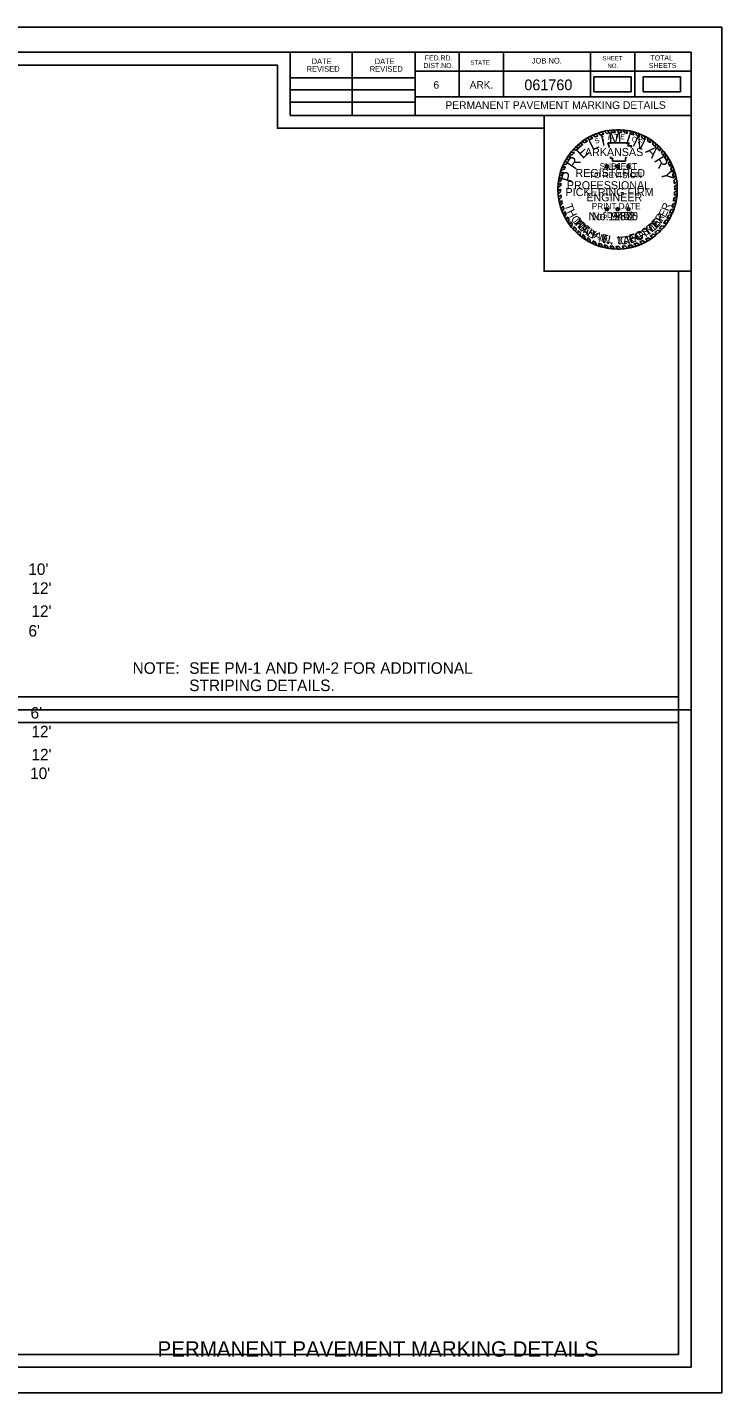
# Model space of a CAD drawing. Extents: x 1369905 to 1370238, y 380119 to 380332.
# Drawn here: x 1370129.6 to 1370238, y 380119.1 to 380332.4 of the extents above; entities that cross this region are included whole.
import ezdxf

# ---------------------------------------------------------------- set-up
doc = ezdxf.new("R2010")
doc.units = 0
for name, color, linetype in [('Default', 7, 'Continuous'), ('R_Border', 7, 'Continuous'), ('R_Border Notes', 7, 'Continuous'), ('R_Border Plan-Plan', 7, 'Continuous'), ('R_Border Title', 7, 'Continuous'), ('R_No Plot', 7, 'Continuous'), ('STAMP_PE_CRAFTON', 7, 'Continuous'), ('STAMP_PE_FOSTER', 7, 'Continuous'), ('STAMP_PE_SEAL-INFO', 7, 'Continuous'), ('STAMP_PE_TAEGTMEYER', 7, 'Continuous'), ('STAMP_PE_TXT', 7, 'Continuous'), ('STAMP_PRELIMINARY', 7, 'Continuous')]:
    doc.layers.add(name, color=color, linetype=linetype)

msp = doc.modelspace()

# ---------------------------------------------------------------- linework, layer by layer
at = {"layer": 'Default'}
for points in [[(1370218.08, 380322.36), (1370223.91, 380322.36), (1370223.91, 380324.67), (1370218.08, 380324.67)], [(1370225.75, 380322.36), (1370231.58, 380322.36), (1370231.58, 380324.67), (1370225.75, 380324.67)]]:
    msp.add_lwpolyline(points, close=True, dxfattribs=at)
at = {"layer": 'R_Border'}
for p, q in [((1369917.1, 380328.52), (1370233.28, 380328.52)), ((1370170.64, 380318.64), (1370170.64, 380328.52)), ((1370180.32, 380318.64), (1370180.32, 380328.52)), ((1370190.18, 380328.52), (1370190.18, 380318.64)), ((1370197.02, 380328.52), (1370197.02, 380321.58)), ((1370203.96, 380328.52), (1370203.96, 380321.58)), ((1370217.54, 380328.52), (1370217.54, 380321.58)), ((1370224.48, 380328.52), (1370224.48, 380321.58)), ((1370233.28, 380123.06), (1370233.28, 380328.52)), ((1370233.28, 380325.58), (1370190.18, 380325.58)), ((1370233.28, 380325.6), (1370233.28, 380325.6)), ((1370170.64, 380324.5), (1370190.18, 380324.5)), ((1370170.64, 380322.64), (1370190.18, 380322.64)), ((1370233.28, 380321.58), (1370190.18, 380321.58)), ((1370193.14, 380321.58), (1370233.28, 380321.58)), ((1370170.64, 380320.7), (1370190.18, 380320.7)), ((1370233.28, 380318.64), (1370170.64, 380318.64)), ((1370233.28, 380123.06), (1369917.1, 380123.06))]:
    msp.add_line(p, q, dxfattribs=at)
at = {"layer": 'R_Border Plan-Plan'}
msp.add_line((1369917.1, 380225.79), (1370233.28, 380225.79), dxfattribs=at)
at = {"layer": 'R_No Plot'}
for points in [[(1369904.69, 380332.42), (1370238.03, 380332.42), (1370238.03, 380119.08), (1369904.69, 380119.08)], [(1370231.28, 380227.79), (1369919.1, 380227.79), (1369919.1, 380326.52), (1370168.64, 380326.52), (1370168.64, 380316.64), (1370186.18, 380316.64), (1370210.28, 380316.64), (1370210.28, 380294.31), (1370231.28, 380294.31)], [(1369919.1, 380326.52), (1370168.64, 380326.52), (1370168.64, 380316.64), (1370186.18, 380316.64), (1370210.28, 380316.64), (1370210.28, 380294.31), (1370231.28, 380294.31), (1370231.28, 380125.06), (1369919.1, 380125.06)], [(1370210.28, 380318.64), (1370233.28, 380318.64), (1370233.28, 380294.31), (1370210.28, 380294.31)], [(1369919.1, 380223.79), (1370231.28, 380223.79), (1370231.28, 380125.06), (1369919.1, 380125.06)]]:
    msp.add_lwpolyline(points, close=True, dxfattribs=at)
at = {"layer": 'STAMP_PE_SEAL-INFO'}
for p, q in [((1370216.62, 380314.85), (1370217.06, 380314.65)), ((1370217, 380315.09), (1370217.43, 380314.87)), ((1370217.45, 380315.34), (1370217.91, 380315.12)), ((1370217.88, 380315.55), (1370218.27, 380315.28)), ((1370218.39, 380315.77), (1370218.68, 380315.44)), ((1370218.74, 380315.9), (1370219.12, 380315.59)), ((1370219.33, 380316.08), (1370219.62, 380315.73)), ((1370219.72, 380316.18), (1370220.07, 380315.83)), ((1370220.2, 380316.27), (1370220.5, 380315.91)), ((1370220.71, 380316.35), (1370220.99, 380315.96)), ((1370221.45, 380315.99), (1370221.14, 380316.39)), ((1370221.95, 380316), (1370221.67, 380316.41)), ((1370222.41, 380315.98), (1370222.15, 380316.4)), ((1370222.91, 380315.93), (1370222.62, 380316.37)), ((1370223.34, 380315.86), (1370223.08, 380316.32)), ((1370223.9, 380315.74), (1370223.72, 380316.2)), ((1370224.3, 380315.63), (1370224.14, 380316.1)), ((1370224.75, 380315.49), (1370224.61, 380315.97)), ((1370225.17, 380315.33), (1370225.03, 380315.82)), ((1370225.63, 380315.12), (1370225.53, 380315.62)), ((1370226.08, 380314.89), (1370225.99, 380315.4)), ((1370226.47, 380314.67), (1370226.43, 380315.17)), ((1370226.9, 380314.38), (1370226.87, 380314.89)), ((1370214.47, 380312.88), (1370215.02, 380312.9)), ((1370214.82, 380313.29), (1370215.34, 380313.25)), ((1370215.14, 380313.63), (1370215.68, 380313.59)), ((1370215.47, 380313.95), (1370215.93, 380313.82)), ((1370215.82, 380314.25), (1370216.35, 380314.15)), ((1370216.2, 380314.58), (1370216.65, 380314.38)), ((1370220.25, 380314.38), (1370223.59, 380314.38)), ((1370220.37, 380314.07), (1370220.25, 380314.38)), ((1370220.48, 380313.77), (1370220.37, 380314.07)), ((1370220.48, 380313.66), (1370220.48, 380313.77)), ((1370223.59, 380314.38), (1370223.37, 380313.88)), ((1370223.37, 380313.88), (1370224, 380313.88)), ((1370224, 380313.88), (1370223.86, 380313.66)), ((1370227.26, 380314.11), (1370227.29, 380314.6)), ((1370227.71, 380313.74), (1370227.73, 380314.26)), ((1370228.02, 380313.45), (1370228.09, 380313.95)), ((1370228.38, 380313.07), (1370228.45, 380313.6)), ((1370228.65, 380312.76), (1370228.79, 380313.23)), ((1370228.98, 380312.34), (1370229.11, 380312.84)), ((1370213.11, 380310.52), (1370213.61, 380310.66)), ((1370213.29, 380310.95), (1370213.8, 380311.05)), ((1370213.48, 380311.34), (1370213.98, 380311.4)), ((1370213.71, 380311.76), (1370214.2, 380311.78)), ((1370213.96, 380312.16), (1370214.47, 380312.2)), ((1370214.19, 380312.51), (1370214.7, 380312.5)), ((1370220.67, 380311.95), (1370220.65, 380312.17)), ((1370220.99, 380311.95), (1370220.67, 380311.95)), ((1370220.99, 380311.52), (1370220.99, 380311.95)), ((1370223.02, 380311.52), (1370220.99, 380311.52)), ((1370223.03, 380311.86), (1370223.02, 380311.52)), ((1370223.11, 380312.17), (1370223.03, 380311.86)), ((1370229.2, 380312.03), (1370229.37, 380312.49)), ((1370229.5, 380311.53), (1370229.69, 380312.02)), ((1370229.7, 380311.16), (1370229.93, 380311.61)), ((1370229.93, 380310.68), (1370230.16, 380311.16)), ((1370230.08, 380310.34), (1370230.34, 380310.77)), ((1370212.98, 380308.49), (1370212.53, 380308.27)), ((1370213.06, 380308.95), (1370212.6, 380308.7)), ((1370212.7, 380309.2), (1370213.17, 380309.39)), ((1370212.8, 380309.61), (1370213.28, 380309.78)), ((1370212.96, 380310.11), (1370213.44, 380310.25)), ((1370230.27, 380309.79), (1370230.54, 380310.27)), ((1370230.38, 380309.43), (1370230.67, 380309.88)), ((1370230.51, 380308.87), (1370230.83, 380309.32)), ((1370230.58, 380308.49), (1370230.93, 380308.84)), ((1370212.88, 380307.63), (1370212.46, 380307.38)), ((1370212.86, 380307.14), (1370212.46, 380306.8)), ((1370212.92, 380308.06), (1370212.48, 380307.78)), ((1370212.87, 380306.73), (1370212.48, 380306.41)), ((1370230.64, 380306.13), (1370231.07, 380306.39)), ((1370230.65, 380307.98), (1370231.02, 380308.32)), ((1370230.68, 380307.56), (1370231.07, 380307.85)), ((1370230.68, 380306.64), (1370231.1, 380306.92)), ((1370230.69, 380307.04), (1370231.1, 380307.37)), ((1370212.9, 380306.24), (1370212.53, 380305.88)), ((1370212.96, 380305.81), (1370212.6, 380305.44)), ((1370213.03, 380305.35), (1370212.7, 380304.98)), ((1370213.13, 380304.93), (1370212.82, 380304.52)), ((1370213.25, 380304.48), (1370212.96, 380304.07)), ((1370230.24, 380304.3), (1370230.73, 380304.5)), ((1370230.39, 380304.79), (1370230.86, 380304.99)), ((1370230.5, 380305.24), (1370230.95, 380305.44)), ((1370230.59, 380305.74), (1370231.03, 380305.96)), ((1370213.39, 380304.06), (1370213.11, 380303.65)), ((1370213.56, 380303.63), (1370213.3, 380303.21)), ((1370213.73, 380303.25), (1370213.5, 380302.79)), ((1370213.97, 380302.79), (1370213.78, 380302.3)), ((1370214.2, 380302.39), (1370214.02, 380301.92)), ((1370214.4, 380302.08), (1370214.29, 380301.53)), ((1370229.29, 380302.29), (1370229.77, 380302.28)), ((1370229.46, 380302.57), (1370229.96, 380302.62)), ((1370229.73, 380303.07), (1370230.22, 380303.14)), ((1370229.9, 380303.4), (1370230.38, 380303.5)), ((1370230.11, 380303.92), (1370230.59, 380304.05)), ((1370214.68, 380301.69), (1370214.58, 380301.16)), ((1370214.99, 380301.31), (1370214.9, 380300.79)), ((1370215.29, 380300.97), (1370215.23, 380300.45)), ((1370215.61, 380300.65), (1370215.58, 380300.12)), ((1370215.96, 380300.33), (1370215.95, 380299.8)), ((1370216.32, 380300.04), (1370216.34, 380299.51)), ((1370227.33, 380300.11), (1370227.8, 380299.97)), ((1370227.6, 380300.33), (1370228.07, 380300.21)), ((1370228, 380300.71), (1370228.45, 380300.57)), ((1370228.26, 380300.97), (1370228.74, 380300.88)), ((1370228.64, 380301.4), (1370229.1, 380301.32)), ((1370228.95, 380301.79), (1370229.46, 380301.8)), ((1370216.66, 380299.79), (1370216.69, 380299.27)), ((1370217.08, 380299.51), (1370217.14, 380299)), ((1370217.43, 380299.3), (1370217.53, 380298.79)), ((1370217.91, 380299.05), (1370218.07, 380298.53)), ((1370218.29, 380298.88), (1370218.46, 380298.37)), ((1370218.78, 380298.69), (1370218.99, 380298.19)), ((1370219.19, 380298.56), (1370219.42, 380298.07)), ((1370219.7, 380298.42), (1370219.91, 380297.95)), ((1370220.09, 380298.33), (1370220.34, 380297.87)), ((1370220.6, 380298.25), (1370220.84, 380297.81)), ((1370221.03, 380298.2), (1370221.31, 380297.77)), ((1370221.52, 380298.18), (1370221.82, 380297.76)), ((1370221.98, 380298.17), (1370222.32, 380297.78)), ((1370222.49, 380298.2), (1370222.82, 380297.82)), ((1370222.93, 380298.25), (1370223.31, 380297.89)), ((1370223.38, 380298.32), (1370223.77, 380297.98)), ((1370223.87, 380298.42), (1370224.25, 380298.1)), ((1370224.33, 380298.54), (1370224.75, 380298.25)), ((1370224.82, 380298.71), (1370225.27, 380298.44)), ((1370225.24, 380298.87), (1370225.67, 380298.61)), ((1370225.7, 380299.08), (1370226.19, 380298.87)), ((1370226.11, 380299.29), (1370226.53, 380299.06)), ((1370226.52, 380299.54), (1370226.97, 380299.34)), ((1370226.87, 380299.77), (1370227.31, 380299.58))]:
    msp.add_line(p, q, dxfattribs=at)
for radius, start, end in [(9.32, 123.6199, 126.5906), (9.32, 117.6544, 120.8099), (8.91, 115.6869, 119.1583), (9.32, 111.3124, 114.7026), (8.91, 110.3086, 113.1659), (9.32, 105.2339, 109.0352), (8.91, 104.0352, 107.3615), (9.32, 99.7525, 102.7765), (8.91, 98.258, 101.0329), (9.32, 93.9381, 96.5517), (8.91, 92.1102, 95.0367), (9.32, 87.7298, 90.6707), (8.91, 85.9628, 88.9097), (9.32, 81.9732, 84.8236), (8.91, 79.9264, 82.696), (9.32, 75.3125, 77.9426), (8.91, 73.5575, 76.2314), (9.32, 69.6061, 72.3058), (8.91, 67.6248, 70.504), (9.32, 63.1329, 66.2704), (8.91, 61.1558, 64.3784), (9.32, 56.9003, 60.0942), (9.32, 141.6056, 144.4486), (8.91, 139.301, 142.5873), (9.32, 135.4021, 138.3031), (8.91, 133.1331, 136.2562), (9.32, 129.7326, 132.5376), (8.91, 127.5297, 130.9683), (8.91, 121.9746, 125.11), (8.91, 54.9238, 58.2702), (8.91, 48.3016, 52.0395), (9.32, 50.3492, 53.7159), (8.91, 42.2212, 45.5512), (9.32, 44.3405, 47.3929), (8.91, 36.135, 39.5311), (9.32, 38.1247, 41.2316), (9.32, 152.864, 155.5189), (8.91, 156.3402, 159.2319), (9.32, 147.0072, 149.899), (8.91, 151.0315, 153.573), (8.91, 145.0197, 148.2104), (8.91, 29.9032, 33.6645), (9.32, 31.9614, 35.4294), (8.91, 23.7732, 27.2211), (9.32, 25.9391, 29.0125), (9.32, 19.9538, 23.3141), (9.32, 170.0003, 172.6878), (9.32, 164.3068, 166.894), (9.32, 158.4077, 161.0701), (8.91, 167.9048, 170.9039), (8.91, 162.4331, 165.0013), (8.91, 17.6802, 21.4251), (8.91, 11.5444, 15.2364), (8.91, 5.7599, 9.0606), (9.32, 13.8421, 17.4447), (9.32, 7.5852, 10.8621), (9.32, 175.7409, 178.2066), (9.32, 181.7251, 184.1626), (8.91, 179.6454, 182.2633), (8.91, 173.73, 176.4734), (8.91, 353.8632, 357.1274), (8.91, 359.7329, 3.0639), (9.32, 1.7215, 4.7268), (9.32, 355.7156, 358.9569), (9.32, 187.4204, 190.1927), (9.32, 193.0369, 195.9973), (8.91, 185.4539, 188.234), (8.91, 191.2274, 193.9858), (8.91, 196.9675, 199.8353), (8.91, 341.777, 345.0925), (8.91, 348.0778, 351.3435), (9.32, 343.8925, 347.035), (9.32, 349.8305, 353.0885), (9.32, 198.8967, 201.6281), (9.32, 204.5479, 207.4328), (8.91, 202.7761, 205.4791), (9.32, 210.8636, 213.6571), (8.91, 208.7883, 211.7934), (8.91, 214.1838, 217.2747), (8.91, 323.5851, 327.4407), (8.91, 329.5549, 333.2076), (9.32, 325.4405, 328.9872), (8.91, 335.6038, 339.1858), (9.32, 331.4037, 334.9332), (9.32, 337.3837, 340.9933), (9.32, 216.6115, 219.491), (9.32, 222.48, 225.3801), (8.91, 220.3909, 223.3056), (9.32, 228.3665, 231.348), (8.91, 226.2494, 229.2407), (8.91, 232.229, 234.9336), (8.91, 304.823, 308.5143), (9.32, 306.3721, 310.208), (8.91, 310.7744, 314.3161), (9.32, 312.4518, 315.6633), (8.91, 316.6531, 320.3711), (9.32, 318.2846, 321.8043), (9.32, 234.295, 236.9452), (8.91, 238.2223, 240.8353), (9.32, 240.1977, 242.8613), (8.91, 244.3204, 246.9486), (9.32, 246.576, 249.1558), (8.91, 250.3491, 253.1216), (9.32, 252.5967, 255.3252), (8.91, 256.505, 259.1192), (9.32, 258.4433, 261.1398), (8.91, 262.3783, 265.2012), (9.32, 264.1978, 267.1009), (8.91, 268.3215, 271.277), (9.32, 270.2548, 273.3361), (8.91, 274.6157, 277.4486), (9.32, 276.4239, 279.4357), (8.91, 280.3459, 283.5814), (9.32, 282.3199, 285.3702), (8.91, 286.6423, 289.9783), (9.32, 288.5709, 291.9733), (8.91, 292.8745, 296.1185), (9.32, 294.6481, 298.2166), (8.91, 299.0768, 302.1724), (9.32, 300.621, 303.8703)]:
    msp.add_arc((1370221.78, 380307.09), radius, start, end, dxfattribs=at)
at = {"layer": 'STAMP_PE_TXT'}
for p, q in [((1370219.96, 380310.66), (1370219.76, 380310.8)), ((1370219.76, 380310.8), (1370220, 380310.8)), ((1370219.88, 380310.42), (1370219.96, 380310.66)), ((1370220.08, 380310.57), (1370219.88, 380310.42)), ((1370220, 380310.8), (1370220.08, 380311.03)), ((1370220.08, 380311.03), (1370220.16, 380310.8)), ((1370220.28, 380310.42), (1370220.08, 380310.57)), ((1370220.16, 380310.8), (1370220.4, 380310.8)), ((1370220.4, 380310.8), (1370220.2, 380310.66)), ((1370220.2, 380310.66), (1370220.28, 380310.42)), ((1370221.65, 380310.66), (1370221.46, 380310.8)), ((1370221.46, 380310.8), (1370221.7, 380310.8)), ((1370221.58, 380310.42), (1370221.65, 380310.66)), ((1370221.78, 380310.57), (1370221.58, 380310.42)), ((1370221.7, 380310.8), (1370221.78, 380311.03)), ((1370221.78, 380311.03), (1370221.85, 380310.8)), ((1370221.98, 380310.42), (1370221.78, 380310.57)), ((1370221.85, 380310.8), (1370222.1, 380310.8)), ((1370222.1, 380310.8), (1370221.9, 380310.66)), ((1370221.9, 380310.66), (1370221.98, 380310.42)), ((1370223.35, 380310.66), (1370223.15, 380310.8)), ((1370223.15, 380310.8), (1370223.4, 380310.8)), ((1370223.28, 380310.42), (1370223.35, 380310.66)), ((1370223.48, 380310.57), (1370223.28, 380310.42)), ((1370223.4, 380310.8), (1370223.48, 380311.03)), ((1370223.48, 380311.03), (1370223.55, 380310.8)), ((1370223.67, 380310.42), (1370223.48, 380310.57)), ((1370223.55, 380310.8), (1370223.8, 380310.8)), ((1370223.8, 380310.8), (1370223.6, 380310.66)), ((1370223.6, 380310.66), (1370223.67, 380310.42)), ((1370220, 380304.09), (1370220.08, 380304.33)), ((1370220.08, 380304.33), (1370220.16, 380304.09)), ((1370221.7, 380304.09), (1370221.78, 380304.33)), ((1370221.78, 380304.33), (1370221.85, 380304.09)), ((1370223.4, 380304.09), (1370223.48, 380304.33)), ((1370223.48, 380304.33), (1370223.55, 380304.09)), ((1370219.96, 380303.95), (1370219.76, 380304.09)), ((1370219.76, 380304.09), (1370220, 380304.09)), ((1370219.88, 380303.72), (1370219.96, 380303.95)), ((1370220.08, 380303.86), (1370219.88, 380303.72)), ((1370220.28, 380303.72), (1370220.08, 380303.86)), ((1370220.16, 380304.09), (1370220.4, 380304.09)), ((1370220.4, 380304.09), (1370220.2, 380303.95)), ((1370220.2, 380303.95), (1370220.28, 380303.72)), ((1370221.65, 380303.95), (1370221.46, 380304.09)), ((1370221.46, 380304.09), (1370221.7, 380304.09)), ((1370221.58, 380303.72), (1370221.65, 380303.95)), ((1370221.78, 380303.86), (1370221.58, 380303.72)), ((1370221.98, 380303.72), (1370221.78, 380303.86)), ((1370221.85, 380304.09), (1370222.1, 380304.09)), ((1370222.1, 380304.09), (1370221.9, 380303.95)), ((1370221.9, 380303.95), (1370221.98, 380303.72)), ((1370223.35, 380303.95), (1370223.15, 380304.09)), ((1370223.15, 380304.09), (1370223.4, 380304.09)), ((1370223.28, 380303.72), (1370223.35, 380303.95)), ((1370223.48, 380303.86), (1370223.28, 380303.72)), ((1370223.67, 380303.72), (1370223.48, 380303.86)), ((1370223.55, 380304.09), (1370223.8, 380304.09)), ((1370223.8, 380304.09), (1370223.6, 380303.95)), ((1370223.6, 380303.95), (1370223.67, 380303.72))]:
    msp.add_line(p, q, dxfattribs=at)
at = {"layer": 'STAMP_PRELIMINARY'}
msp.add_circle((1370221.78, 380307.09), 9.32, dxfattribs=at)

# ---------------------------------------------------------------- texts
at = {"layer": 'Default'}
for s, p in [("10'", (1370129.73, 380246.85)), ("12'", (1370130.22, 380243.89)), ("12'", (1370130.22, 380240.29)), ("6'", (1370129.75, 380237.22)), ("6'", (1370130.08, 380224.4)), ("12'", (1370130.22, 380221.48)), ("12'", (1370130.22, 380217.88)), ("10'", (1370130.01, 380214.96))]:
    msp.add_text(s, height=1.8, rotation=360, dxfattribs=at).set_placement(p)
for s, p in [('NOTE:', (1370146.02, 380231.4)), ('SEE PM-1 AND PM-2 FOR ADDITIONAL', (1370154.87, 380231.4)), ('STRIPING DETAILS.', (1370154.87, 380228.7))]:
    msp.add_text(s, height=1.8, dxfattribs=at).set_placement(p)
at = {"layer": 'R_Border'}
for s, height, p in [('FED.RD.', 0.782, (1370191.66, 380327.24)), ('JOB NO.', 0.879, (1370208.36, 380326.76)), ('SHEET', 0.684, (1370219.4, 380327.24)), ('TOTAL', 0.782, (1370226.92, 380327.24)), ('REVISED', 0.879, (1370173.2, 380325.48)), ('DATE', 0.879, (1370173.98, 380326.66)), ('REVISED', 0.879, (1370183.06, 380325.48)), ('DATE', 0.879, (1370183.84, 380326.66)), ('DIST.NO.', 0.782, (1370191.46, 380326.06)), ('STATE', 0.684, (1370198.78, 380326.56)), ('NO.', 0.684, (1370220.18, 380326.06)), ('SHEETS', 0.782, (1370226.64, 380326.06)), ('6', 1.17, (1370193.02, 380322.84)), ('ARK.', 1.172, (1370198.68, 380322.84))]:
    msp.add_text(s, height=height, dxfattribs=at).set_placement(p)
at = {"layer": 'R_Border Notes'}
for s, height, p in [('061760', 1.68, (1370207.21, 380322.59)), ('PERMANENT PAVEMENT MARKING DETAILS', 1.2, (1370194.88, 380319.66))]:
    msp.add_text(s, height=height, dxfattribs=at).set_placement(p)
at = {"layer": 'R_Border Title'}
msp.add_text('PERMANENT PAVEMENT MARKING DETAILS', height=2.4, dxfattribs=at).set_placement((1370149.92, 380124.71))
at = {"layer": 'STAMP_PE_CRAFTON'}
for s, rotation, p in [('T', 310.7442, (1370214.74, 380301.98)), ('N', 49.2411, (1370228.06, 380301.11)), ('O', 317.6422, (1370215.41, 380301.17)), ('N', 324.4537, (1370216.26, 380300.39)), ('Y', 331.1686, (1370217.29, 380299.67)), ('N', 347.4752, (1370219.34, 380298.75)), ('R', 14.8189, (1370223.35, 380298.54)), ('A', 20.5125, (1370224.46, 380298.84)), ('F', 28.7821, (1370225.44, 380299.21)), ('T', 34.1136, (1370226.35, 380299.72)), ('O', 41.8391, (1370227.21, 380300.33)), ('.', 356.8926, (1370220.57, 380298.48)), ('C', 6.0117, (1370222.25, 380298.43))]:
    msp.add_text(s, height=1.25, rotation=rotation, dxfattribs=at).set_placement(p)
msp.add_text('No. 12370', height=1.25, dxfattribs=at).set_placement((1370217.24, 380302.28))
at = {"layer": 'STAMP_PE_FOSTER'}
for s, rotation, p in [('M', 308.339, (1370214.89, 380302.11)), ('E', 46.9613, (1370227.78, 380301.08)), ('R', 54.5031, (1370228.5, 380301.9)), ('I', 314.1842, (1370215.69, 380301.17)), ('C', 319.8733, (1370216.05, 380300.82)), ('H', 327.7235, (1370216.97, 380300.08)), ('A', 335.7276, (1370217.96, 380299.5)), ('E', 343.5779, (1370219.09, 380299.03)), ('L', 350.8115, (1370220.15, 380298.75)), ('F', 15.8691, (1370223.81, 380298.84)), ('O', 23.719, (1370224.86, 380299.17)), ('S', 31.7234, (1370225.97, 380299.7)), ('T', 39.4194, (1370226.92, 380300.33)), ('L', 1.2666, (1370221.69, 380298.59)), ('.', 6.8035, (1370222.74, 380298.65))]:
    msp.add_text(s, height=1.2, rotation=rotation, dxfattribs=at).set_placement(p)
msp.add_text('No. 9402', height=1.25, dxfattribs=at).set_placement((1370217.76, 380302.28))
at = {"layer": 'STAMP_PE_TAEGTMEYER'}
for s, rotation, p in [('T', 289.646, (1370213.47, 380304.6)), ('R', 69.57, (1370229.72, 380303.6)), ('H', 296.7339, (1370213.83, 380303.61)), ('O', 303.7708, (1370214.42, 380302.5)), ('M', 314.2033, (1370215.08, 380301.55)), ('E', 46.8094, (1370227.82, 380300.86)), ('Y', 53.9986, (1370228.56, 380301.68)), ('E', 63.0984, (1370229.22, 380302.62)), ('A', 321.0594, (1370216.04, 380300.59)), ('S', 327.8239, (1370216.87, 380299.94)), ('N', 344.2727, (1370218.76, 380298.94)), ('E', 17.6836, (1370223.73, 380298.62)), ('G', 23.3052, (1370224.78, 380298.95)), ('T', 31.466, (1370225.88, 380299.44)), ('M', 39.3, (1370226.78, 380299.98)), ('.', 350.6464, (1370219.98, 380298.6)), ('T', 3.0061, (1370221.64, 380298.41)), ('A', 8.9826, (1370222.69, 380298.46))]:
    msp.add_text(s, height=1.25, rotation=rotation, dxfattribs=at).set_placement(p)
msp.add_text('No. 19605', height=1.25, dxfattribs=at).set_placement((1370217.24, 380302.28))
at = {"layer": 'STAMP_PE_TXT'}
for s, rotation, p in [('S', 23.5541, (1370218.38, 380314.19)), ('T', 16.311, (1370219.3, 380314.56)), ('A', 9.0679, (1370220.26, 380314.81)), ('T', 1.8248, (1370221.25, 380314.94)), ('E', 355.2002, (1370222.16, 380314.95)), ('O', 342.2506, (1370223.88, 380314.68)), ('F', 335.0075, (1370224.85, 380314.34))]:
    msp.add_text(s, height=0.781, rotation=rotation, dxfattribs=at).set_placement(p)
for s, p in [('ARKANSAS', (1370216.67, 380312.3)), ('REGISTERED', (1370215.19, 380309.03)), ('PROFESSIONAL', (1370213.85, 380307.12)), ('ENGINEER', (1370216.89, 380305.22))]:
    msp.add_text(s, height=1.25, dxfattribs=at).set_placement(p)
at = {"layer": 'STAMP_PRELIMINARY'}
for s, rotation, p in [('L', 25.513, (1370217.79, 380313.11)), ('I', 12.5248, (1370219.32, 380313.87)), ('M', 3.1074, (1370220.41, 380314.18)), ('I', 342.3164, (1370222.88, 380314.25)), ('N', 333.9382, (1370223.99, 380313.97)), ('E', 42.3578, (1370216.3, 380311.78)), ('A', 315.6579, (1370226.02, 380312.95)), ('R', 56.2292, (1370215.15, 380310.05)), ('R', 301.3831, (1370227.39, 380311.63)), ('P', 73.913, (1370214.6, 380308.03)), ('Y', 283.2593, (1370228.48, 380309.85))]:
    msp.add_text(s, height=1.8, rotation=rotation, dxfattribs=at).set_placement(p)
for s, height, p in [('SUBJECT', 0.96, (1370218.98, 380310.23)), ('TO REVISION', 0.96, (1370217.31, 380308.85)), ('PICKERING FIRM', 1.25, (1370213.65, 380306.05)), ('PRINT DATE', 0.96, (1370217.74, 380304)), ('$DATE$', 0.96, (1370219.41, 380302.62))]:
    msp.add_text(s, height=height, dxfattribs=at).set_placement(p)

doc.saveas('drawing.dxf')
